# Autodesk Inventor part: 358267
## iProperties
Created: 2006-03
Part Number: 358267
Material: 1.0718.07
Document SubType Name: Modeling
Designer: I.Baliuc
Description: Scheibe
Density: 7.84 g/cm^3
Title: Scheibe
Company: Mayer & Müller AG Schaltgeräte
HalbzeugNorm: DIN 671
Zweck: Schaltrohr Trenner
Abmessung: Rd. 50
Author: T.Messerschmitt
Revision Number: 358267
Keywords: 266468
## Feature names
1. Extrusion2
